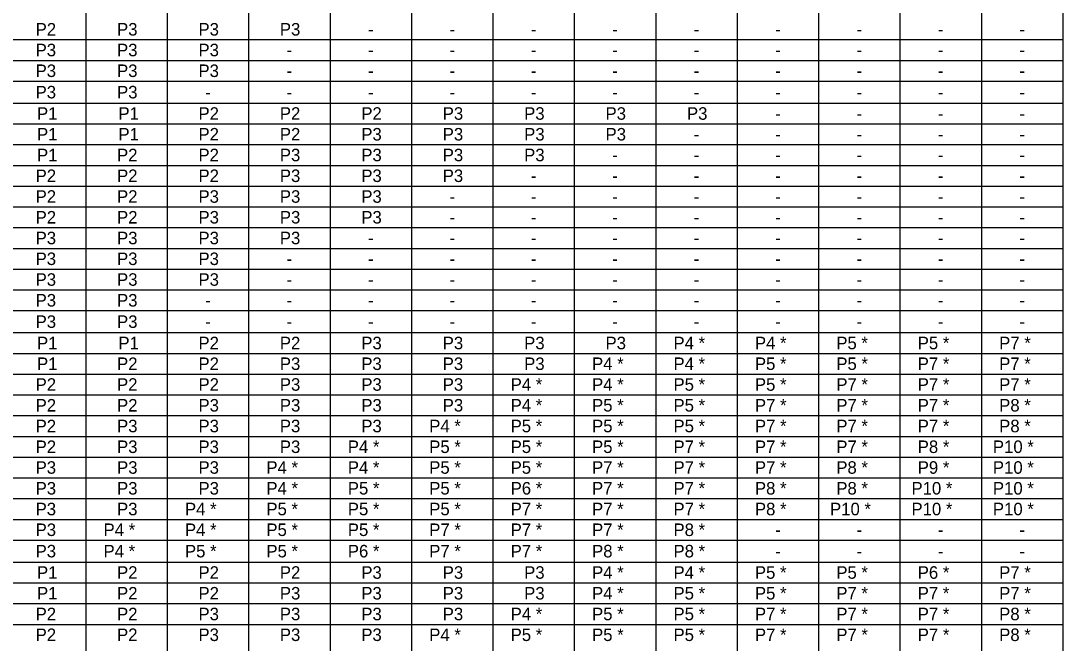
# Model space of a CAD drawing. Extents: x 637580 to 641008, y 294594 to 295782.
# Drawn here: x 638627 to 638876.7, y 295486.9 to 295636 of the extents above; entities that cross this region are included whole.
import ezdxf

# ---------------------------------------------------------------- set-up
doc = ezdxf.new("R2010")
doc.units = 0
doc.layers.add('1', color=7, linetype='Continuous')
doc.layers.add('2', color=7, linetype='Continuous')

msp = doc.modelspace()

# ---------------------------------------------------------------- linework, layer by layer
at = {"layer": '1'}
for p, q in [((638876.73, 295231.34), (638876.73, 295750.63)), ((638642.64, 295231.34), (638642.64, 295735.61)), ((638662.15, 295231.34), (638662.15, 295735.61)), ((638681.66, 295231.34), (638681.66, 295735.61)), ((638701.17, 295231.34), (638701.17, 295735.61)), ((638720.67, 295231.34), (638720.67, 295735.61)), ((638740.18, 295231.34), (638740.18, 295735.61)), ((638759.69, 295231.34), (638759.69, 295735.61)), ((638779.2, 295231.34), (638779.2, 295735.61)), ((638798.7, 295231.34), (638798.7, 295735.61)), ((638818.21, 295231.34), (638818.21, 295735.61)), ((638837.72, 295231.34), (638837.72, 295735.61)), ((638857.23, 295231.34), (638857.23, 295735.61)), ((638509.81, 295616.27), (638876.73, 295616.27)), ((638509.81, 295561.28), (638876.73, 295561.28)), ((638509.81, 295506.29), (638876.73, 295506.29))]:
    msp.add_line(p, q, dxfattribs=at)
at = {"layer": '2'}
for p, q in [((638536.61, 295631.48), (638876.73, 295631.48)), ((638536.61, 295626.51), (638876.73, 295626.51)), ((638536.61, 295621.53), (638876.73, 295621.53)), ((638536.61, 295611.3), (638876.73, 295611.3)), ((638536.61, 295606.32), (638876.73, 295606.32)), ((638536.61, 295601.35), (638876.73, 295601.35)), ((638536.61, 295596.38), (638876.73, 295596.38)), ((638536.61, 295591.41), (638876.73, 295591.41)), ((638536.61, 295586.43), (638876.73, 295586.43)), ((638536.61, 295581.46), (638876.73, 295581.46)), ((638536.61, 295576.49), (638876.73, 295576.49)), ((638536.61, 295571.52), (638876.73, 295571.52)), ((638536.61, 295566.54), (638876.73, 295566.54)), ((638536.61, 295556.31), (638876.73, 295556.31)), ((638536.61, 295551.33), (638876.73, 295551.33)), ((638536.61, 295546.36), (638876.73, 295546.36)), ((638536.61, 295541.39), (638876.73, 295541.39)), ((638536.61, 295536.42), (638876.73, 295536.42)), ((638536.61, 295531.44), (638876.73, 295531.44)), ((638536.61, 295526.47), (638876.73, 295526.47)), ((638536.61, 295521.5), (638876.73, 295521.5)), ((638536.61, 295516.53), (638876.73, 295516.53)), ((638536.61, 295511.55), (638876.73, 295511.55)), ((638536.61, 295501.32), (638876.73, 295501.32)), ((638536.61, 295496.34), (638876.73, 295496.34)), ((638536.61, 295491.37), (638876.73, 295491.37))]:
    msp.add_line(p, q, dxfattribs=at)

# ---------------------------------------------------------------- texts
at = {"layer": '1'}
for s, p in [('P2', (638630.54, 295632.46)), ('P3', (638650.05, 295632.46)), ('P3', (638669.56, 295632.46)), ('P3', (638689.06, 295632.46)), ('-', (638710.19, 295632.46)), ('-', (638729.7, 295632.46)), ('-', (638749.2, 295632.46)), ('-', (638768.71, 295632.46)), ('-', (638788.22, 295632.46)), ('-', (638807.73, 295632.46)), ('-', (638827.23, 295632.46)), ('-', (638846.74, 295632.46)), ('-', (638866.25, 295632.46)), ('P3', (638630.54, 295627.49)), ('P3', (638650.05, 295627.49)), ('P3', (638669.56, 295627.49)), ('-', (638690.68, 295627.49)), ('-', (638710.19, 295627.49)), ('-', (638729.7, 295627.49)), ('-', (638749.2, 295627.49)), ('-', (638768.71, 295627.49)), ('-', (638788.22, 295627.49)), ('-', (638807.73, 295627.49)), ('-', (638827.23, 295627.49)), ('-', (638846.74, 295627.49)), ('-', (638866.25, 295627.49)), ('P3', (638630.54, 295622.52)), ('P3', (638650.05, 295622.52)), ('P3', (638669.56, 295622.52)), ('-', (638690.68, 295622.52)), ('-', (638710.19, 295622.52)), ('-', (638729.7, 295622.52)), ('-', (638749.2, 295622.52)), ('-', (638768.71, 295622.52)), ('-', (638788.22, 295622.52)), ('-', (638807.73, 295622.52)), ('-', (638827.23, 295622.52)), ('-', (638846.74, 295622.52)), ('-', (638866.25, 295622.52)), ('P3', (638630.54, 295617.4)), ('P3', (638650.05, 295617.4)), ('-', (638671.17, 295617.4)), ('-', (638690.68, 295617.4)), ('-', (638710.19, 295617.4)), ('-', (638729.7, 295617.4)), ('-', (638749.2, 295617.4)), ('-', (638768.71, 295617.4)), ('-', (638788.22, 295617.4)), ('-', (638807.73, 295617.4)), ('-', (638827.23, 295617.4)), ('-', (638846.74, 295617.4)), ('-', (638866.25, 295617.4)), ('P1', (638630.88, 295612.28)), ('P1', (638650.39, 295612.28)), ('P2', (638669.56, 295612.28)), ('P2', (638689.06, 295612.28)), ('P2', (638708.57, 295612.28)), ('P3', (638728.08, 295612.28)), ('P3', (638747.59, 295612.28)), ('P3', (638767.09, 295612.28)), ('P3', (638786.6, 295612.28)), ('-', (638807.73, 295612.28)), ('-', (638827.23, 295612.28)), ('-', (638846.74, 295612.28)), ('-', (638866.25, 295612.28)), ('P1', (638630.88, 295607.31)), ('P1', (638650.39, 295607.31)), ('P2', (638669.56, 295607.31)), ('P2', (638689.06, 295607.31)), ('P3', (638708.57, 295607.31)), ('P3', (638728.08, 295607.31)), ('P3', (638747.59, 295607.31)), ('P3', (638767.09, 295607.31)), ('-', (638788.22, 295607.31)), ('-', (638807.73, 295607.31)), ('-', (638827.23, 295607.31)), ('-', (638846.74, 295607.31)), ('-', (638866.25, 295607.31)), ('P1', (638630.88, 295602.34)), ('P2', (638650.05, 295602.34)), ('P2', (638669.56, 295602.34)), ('P3', (638689.06, 295602.34)), ('P3', (638708.57, 295602.34)), ('P3', (638728.08, 295602.34)), ('P3', (638747.59, 295602.34)), ('-', (638768.71, 295602.34)), ('-', (638788.22, 295602.34)), ('-', (638807.73, 295602.34)), ('-', (638827.23, 295602.34)), ('-', (638846.74, 295602.34)), ('-', (638866.25, 295602.34)), ('P2', (638630.54, 295597.36)), ('P2', (638650.05, 295597.36)), ('P2', (638669.56, 295597.36)), ('P3', (638689.06, 295597.36)), ('P3', (638708.57, 295597.36)), ('P3', (638728.08, 295597.36)), ('-', (638749.2, 295597.36)), ('-', (638768.71, 295597.36)), ('-', (638788.22, 295597.36)), ('-', (638807.73, 295597.36)), ('-', (638827.23, 295597.36)), ('-', (638846.74, 295597.36)), ('-', (638866.25, 295597.36)), ('P2', (638630.54, 295592.39)), ('P2', (638650.05, 295592.39)), ('P3', (638669.56, 295592.39)), ('P3', (638689.06, 295592.39)), ('P3', (638708.57, 295592.39)), ('-', (638729.7, 295592.39)), ('-', (638749.2, 295592.39)), ('-', (638768.71, 295592.39)), ('-', (638788.22, 295592.39)), ('-', (638807.73, 295592.39)), ('-', (638827.23, 295592.39)), ('-', (638846.74, 295592.39)), ('-', (638866.25, 295592.39)), ('P2', (638630.54, 295587.42)), ('P2', (638650.05, 295587.42)), ('P3', (638669.56, 295587.42)), ('P3', (638689.06, 295587.42)), ('P3', (638708.57, 295587.42)), ('-', (638729.7, 295587.42)), ('-', (638749.2, 295587.42)), ('-', (638768.71, 295587.42)), ('-', (638788.22, 295587.42)), ('-', (638807.73, 295587.42)), ('-', (638827.23, 295587.42)), ('-', (638846.74, 295587.42)), ('-', (638866.25, 295587.42)), ('P3', (638630.54, 295582.45)), ('P3', (638650.05, 295582.45)), ('P3', (638669.56, 295582.45)), ('P3', (638689.06, 295582.45)), ('-', (638710.19, 295582.45)), ('-', (638729.7, 295582.45)), ('-', (638749.2, 295582.45)), ('-', (638768.71, 295582.45)), ('-', (638788.22, 295582.45)), ('-', (638807.73, 295582.45)), ('-', (638827.23, 295582.45)), ('-', (638846.74, 295582.45)), ('-', (638866.25, 295582.45)), ('P3', (638630.54, 295577.47)), ('P3', (638650.05, 295577.47)), ('P3', (638669.56, 295577.47)), ('-', (638690.68, 295577.47)), ('-', (638710.19, 295577.47)), ('-', (638729.7, 295577.47)), ('-', (638749.2, 295577.47)), ('-', (638768.71, 295577.47)), ('-', (638788.22, 295577.47)), ('-', (638807.73, 295577.47)), ('-', (638827.23, 295577.47)), ('-', (638846.74, 295577.47)), ('-', (638866.25, 295577.47)), ('P3', (638630.54, 295572.5)), ('P3', (638650.05, 295572.5)), ('P3', (638669.56, 295572.5)), ('-', (638690.68, 295572.5)), ('-', (638710.19, 295572.5)), ('-', (638729.7, 295572.5)), ('-', (638749.2, 295572.5)), ('-', (638768.71, 295572.5)), ('-', (638788.22, 295572.5)), ('-', (638807.73, 295572.5)), ('-', (638827.23, 295572.5)), ('-', (638846.74, 295572.5)), ('-', (638866.25, 295572.5)), ('P3', (638630.54, 295567.53)), ('P3', (638650.05, 295567.53)), ('-', (638671.17, 295567.53)), ('-', (638690.68, 295567.53)), ('-', (638710.19, 295567.53)), ('-', (638729.7, 295567.53)), ('-', (638749.2, 295567.53)), ('-', (638768.71, 295567.53)), ('-', (638788.22, 295567.53)), ('-', (638807.73, 295567.53)), ('-', (638827.23, 295567.53)), ('-', (638846.74, 295567.53)), ('-', (638866.25, 295567.53)), ('P3', (638630.54, 295562.41)), ('P3', (638650.05, 295562.41)), ('-', (638671.17, 295562.41)), ('-', (638690.68, 295562.41)), ('-', (638710.19, 295562.41)), ('-', (638729.7, 295562.41)), ('-', (638749.2, 295562.41)), ('-', (638768.71, 295562.41)), ('-', (638788.22, 295562.41)), ('-', (638807.73, 295562.41)), ('-', (638827.23, 295562.41)), ('-', (638846.74, 295562.41)), ('-', (638866.25, 295562.41)), ('P1', (638630.88, 295557.29)), ('P1', (638650.39, 295557.29)), ('P2', (638669.56, 295557.29)), ('P2', (638689.06, 295557.29)), ('P3', (638708.57, 295557.29)), ('P3', (638728.08, 295557.29)), ('P3', (638747.59, 295557.29)), ('P3', (638767.09, 295557.29)), ('P4 *', (638783.37, 295557.29)), ('P4 *', (638802.88, 295557.29)), ('P5 *', (638822.38, 295557.29)), ('P5 *', (638841.89, 295557.29)), ('P7 *', (638861.4, 295557.29)), ('P1', (638630.88, 295552.32)), ('P2', (638650.05, 295552.32)), ('P2', (638669.56, 295552.32)), ('P3', (638689.06, 295552.32)), ('P3', (638708.57, 295552.32)), ('P3', (638728.08, 295552.32)), ('P3', (638747.59, 295552.32)), ('P4 *', (638763.86, 295552.32)), ('P4 *', (638783.37, 295552.32)), ('P5 *', (638802.88, 295552.32)), ('P5 *', (638822.38, 295552.32)), ('P7 *', (638841.89, 295552.32)), ('P7 *', (638861.4, 295552.32)), ('P2', (638630.54, 295547.35)), ('P2', (638650.05, 295547.35)), ('P2', (638669.56, 295547.35)), ('P3', (638689.06, 295547.35)), ('P3', (638708.57, 295547.35)), ('P3', (638728.08, 295547.35)), ('P4 *', (638744.35, 295547.35)), ('P4 *', (638763.86, 295547.35)), ('P5 *', (638783.37, 295547.35)), ('P5 *', (638802.88, 295547.35)), ('P7 *', (638822.38, 295547.35)), ('P7 *', (638841.89, 295547.35)), ('P7 *', (638861.4, 295547.35)), ('P2', (638630.54, 295542.37)), ('P2', (638650.05, 295542.37)), ('P3', (638669.56, 295542.37)), ('P3', (638689.06, 295542.37)), ('P3', (638708.57, 295542.37)), ('P3', (638728.08, 295542.37)), ('P4 *', (638744.35, 295542.37)), ('P5 *', (638763.86, 295542.37)), ('P5 *', (638783.37, 295542.37)), ('P7 *', (638802.88, 295542.37)), ('P7 *', (638822.38, 295542.37)), ('P7 *', (638841.89, 295542.37)), ('P8 *', (638861.4, 295542.37)), ('P2', (638630.54, 295537.4)), ('P3', (638650.05, 295537.4)), ('P3', (638669.56, 295537.4)), ('P3', (638689.06, 295537.4)), ('P3', (638708.57, 295537.4)), ('P4 *', (638724.85, 295537.4)), ('P5 *', (638744.35, 295537.4)), ('P5 *', (638763.86, 295537.4)), ('P5 *', (638783.37, 295537.4)), ('P7 *', (638802.88, 295537.4)), ('P7 *', (638822.38, 295537.4)), ('P7 *', (638841.89, 295537.4)), ('P8 *', (638861.4, 295537.4)), ('P2', (638630.54, 295532.43)), ('P3', (638650.05, 295532.43)), ('P3', (638669.56, 295532.43)), ('P3', (638689.06, 295532.43)), ('P4 *', (638705.34, 295532.43)), ('P5 *', (638724.85, 295532.43)), ('P5 *', (638744.35, 295532.43)), ('P5 *', (638763.86, 295532.43)), ('P7 *', (638783.37, 295532.43)), ('P7 *', (638802.88, 295532.43)), ('P7 *', (638822.38, 295532.43)), ('P8 *', (638841.89, 295532.43)), ('P10 *', (638859.9, 295532.43)), ('P3', (638630.54, 295527.46)), ('P3', (638650.05, 295527.46)), ('P3', (638669.56, 295527.46)), ('P4 *', (638685.83, 295527.46)), ('P4 *', (638705.34, 295527.46)), ('P5 *', (638724.85, 295527.46)), ('P5 *', (638744.35, 295527.46)), ('P7 *', (638763.86, 295527.46)), ('P7 *', (638783.37, 295527.46)), ('P7 *', (638802.88, 295527.46)), ('P8 *', (638822.38, 295527.46)), ('P9 *', (638841.89, 295527.46)), ('P10 *', (638859.9, 295527.46)), ('P3', (638630.54, 295522.48)), ('P3', (638650.05, 295522.48)), ('P3', (638669.56, 295522.48)), ('P4 *', (638685.83, 295522.48)), ('P5 *', (638705.34, 295522.48)), ('P5 *', (638724.85, 295522.48)), ('P6 *', (638744.35, 295522.48)), ('P7 *', (638763.86, 295522.48)), ('P7 *', (638783.37, 295522.48)), ('P8 *', (638802.88, 295522.48)), ('P8 *', (638822.38, 295522.48)), ('P10 *', (638840.39, 295522.48)), ('P10 *', (638859.9, 295522.48)), ('P3', (638630.54, 295517.51)), ('P3', (638650.05, 295517.51)), ('P4 *', (638666.32, 295517.51)), ('P5 *', (638685.83, 295517.51)), ('P5 *', (638705.34, 295517.51)), ('P5 *', (638724.85, 295517.51)), ('P7 *', (638744.35, 295517.51)), ('P7 *', (638763.86, 295517.51)), ('P7 *', (638783.37, 295517.51)), ('P8 *', (638802.88, 295517.51)), ('P10 *', (638820.88, 295517.51)), ('P10 *', (638840.39, 295517.51)), ('P10 *', (638859.9, 295517.51)), ('P3', (638630.54, 295512.54)), ('P4 *', (638646.82, 295512.54)), ('P4 *', (638666.32, 295512.54)), ('P5 *', (638685.83, 295512.54)), ('P5 *', (638705.34, 295512.54)), ('P7 *', (638724.85, 295512.54)), ('P7 *', (638744.35, 295512.54)), ('P7 *', (638763.86, 295512.54)), ('P8 *', (638783.37, 295512.54)), ('-', (638807.73, 295512.54)), ('-', (638827.23, 295512.54)), ('-', (638846.74, 295512.54)), ('-', (638866.25, 295512.54)), ('P3', (638630.54, 295507.42)), ('P4 *', (638646.82, 295507.42)), ('P5 *', (638666.32, 295507.42)), ('P5 *', (638685.83, 295507.42)), ('P6 *', (638705.34, 295507.42)), ('P7 *', (638724.85, 295507.42)), ('P7 *', (638744.35, 295507.42)), ('P8 *', (638763.86, 295507.42)), ('P8 *', (638783.37, 295507.42)), ('-', (638807.73, 295507.42)), ('-', (638827.23, 295507.42)), ('-', (638846.74, 295507.42)), ('-', (638866.25, 295507.42)), ('P1', (638630.88, 295502.3)), ('P2', (638650.05, 295502.3)), ('P2', (638669.56, 295502.3)), ('P2', (638689.06, 295502.3)), ('P3', (638708.57, 295502.3)), ('P3', (638728.08, 295502.3)), ('P3', (638747.59, 295502.3)), ('P4 *', (638763.86, 295502.3)), ('P4 *', (638783.37, 295502.3)), ('P5 *', (638802.88, 295502.3)), ('P5 *', (638822.38, 295502.3)), ('P6 *', (638841.89, 295502.3)), ('P7 *', (638861.4, 295502.3)), ('P1', (638630.88, 295497.33)), ('P2', (638650.05, 295497.33)), ('P2', (638669.56, 295497.33)), ('P3', (638689.06, 295497.33)), ('P3', (638708.57, 295497.33)), ('P3', (638728.08, 295497.33)), ('P3', (638747.59, 295497.33)), ('P4 *', (638763.86, 295497.33)), ('P5 *', (638783.37, 295497.33)), ('P5 *', (638802.88, 295497.33)), ('P7 *', (638822.38, 295497.33)), ('P7 *', (638841.89, 295497.33)), ('P7 *', (638861.4, 295497.33)), ('P2', (638630.54, 295492.36)), ('P2', (638650.05, 295492.36)), ('P3', (638669.56, 295492.36)), ('P3', (638689.06, 295492.36)), ('P3', (638708.57, 295492.36)), ('P3', (638728.08, 295492.36)), ('P4 *', (638744.35, 295492.36)), ('P5 *', (638763.86, 295492.36)), ('P5 *', (638783.37, 295492.36)), ('P7 *', (638802.88, 295492.36)), ('P7 *', (638822.38, 295492.36)), ('P7 *', (638841.89, 295492.36)), ('P8 *', (638861.4, 295492.36)), ('P2', (638630.54, 295487.38)), ('P2', (638650.05, 295487.38)), ('P3', (638669.56, 295487.38)), ('P3', (638689.06, 295487.38)), ('P3', (638708.57, 295487.38)), ('P4 *', (638724.85, 295487.38)), ('P5 *', (638744.35, 295487.38)), ('P5 *', (638763.86, 295487.38)), ('P5 *', (638783.37, 295487.38)), ('P7 *', (638802.88, 295487.38)), ('P7 *', (638822.38, 295487.38)), ('P7 *', (638841.89, 295487.38)), ('P8 *', (638861.4, 295487.38))]:
    msp.add_text(s, height=3, dxfattribs=at).set_placement(p)

doc.saveas('drawing.dxf')
